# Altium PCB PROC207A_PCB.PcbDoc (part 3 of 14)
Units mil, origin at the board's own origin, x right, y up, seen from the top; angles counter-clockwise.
Board outline 4094.49 x 3724.79 mil, 8 copper layers (Top Layer, L2_GND1, L3_SIG1, L4_PWR1, L5_PWR2, L6_SIG2, L7_GND2, Bottom Layer), stack 58.1 mil thick; 584 components, 399 nets, 8440 pads, 5258 vias.
Unrouted connection lines stored in the file: 9.
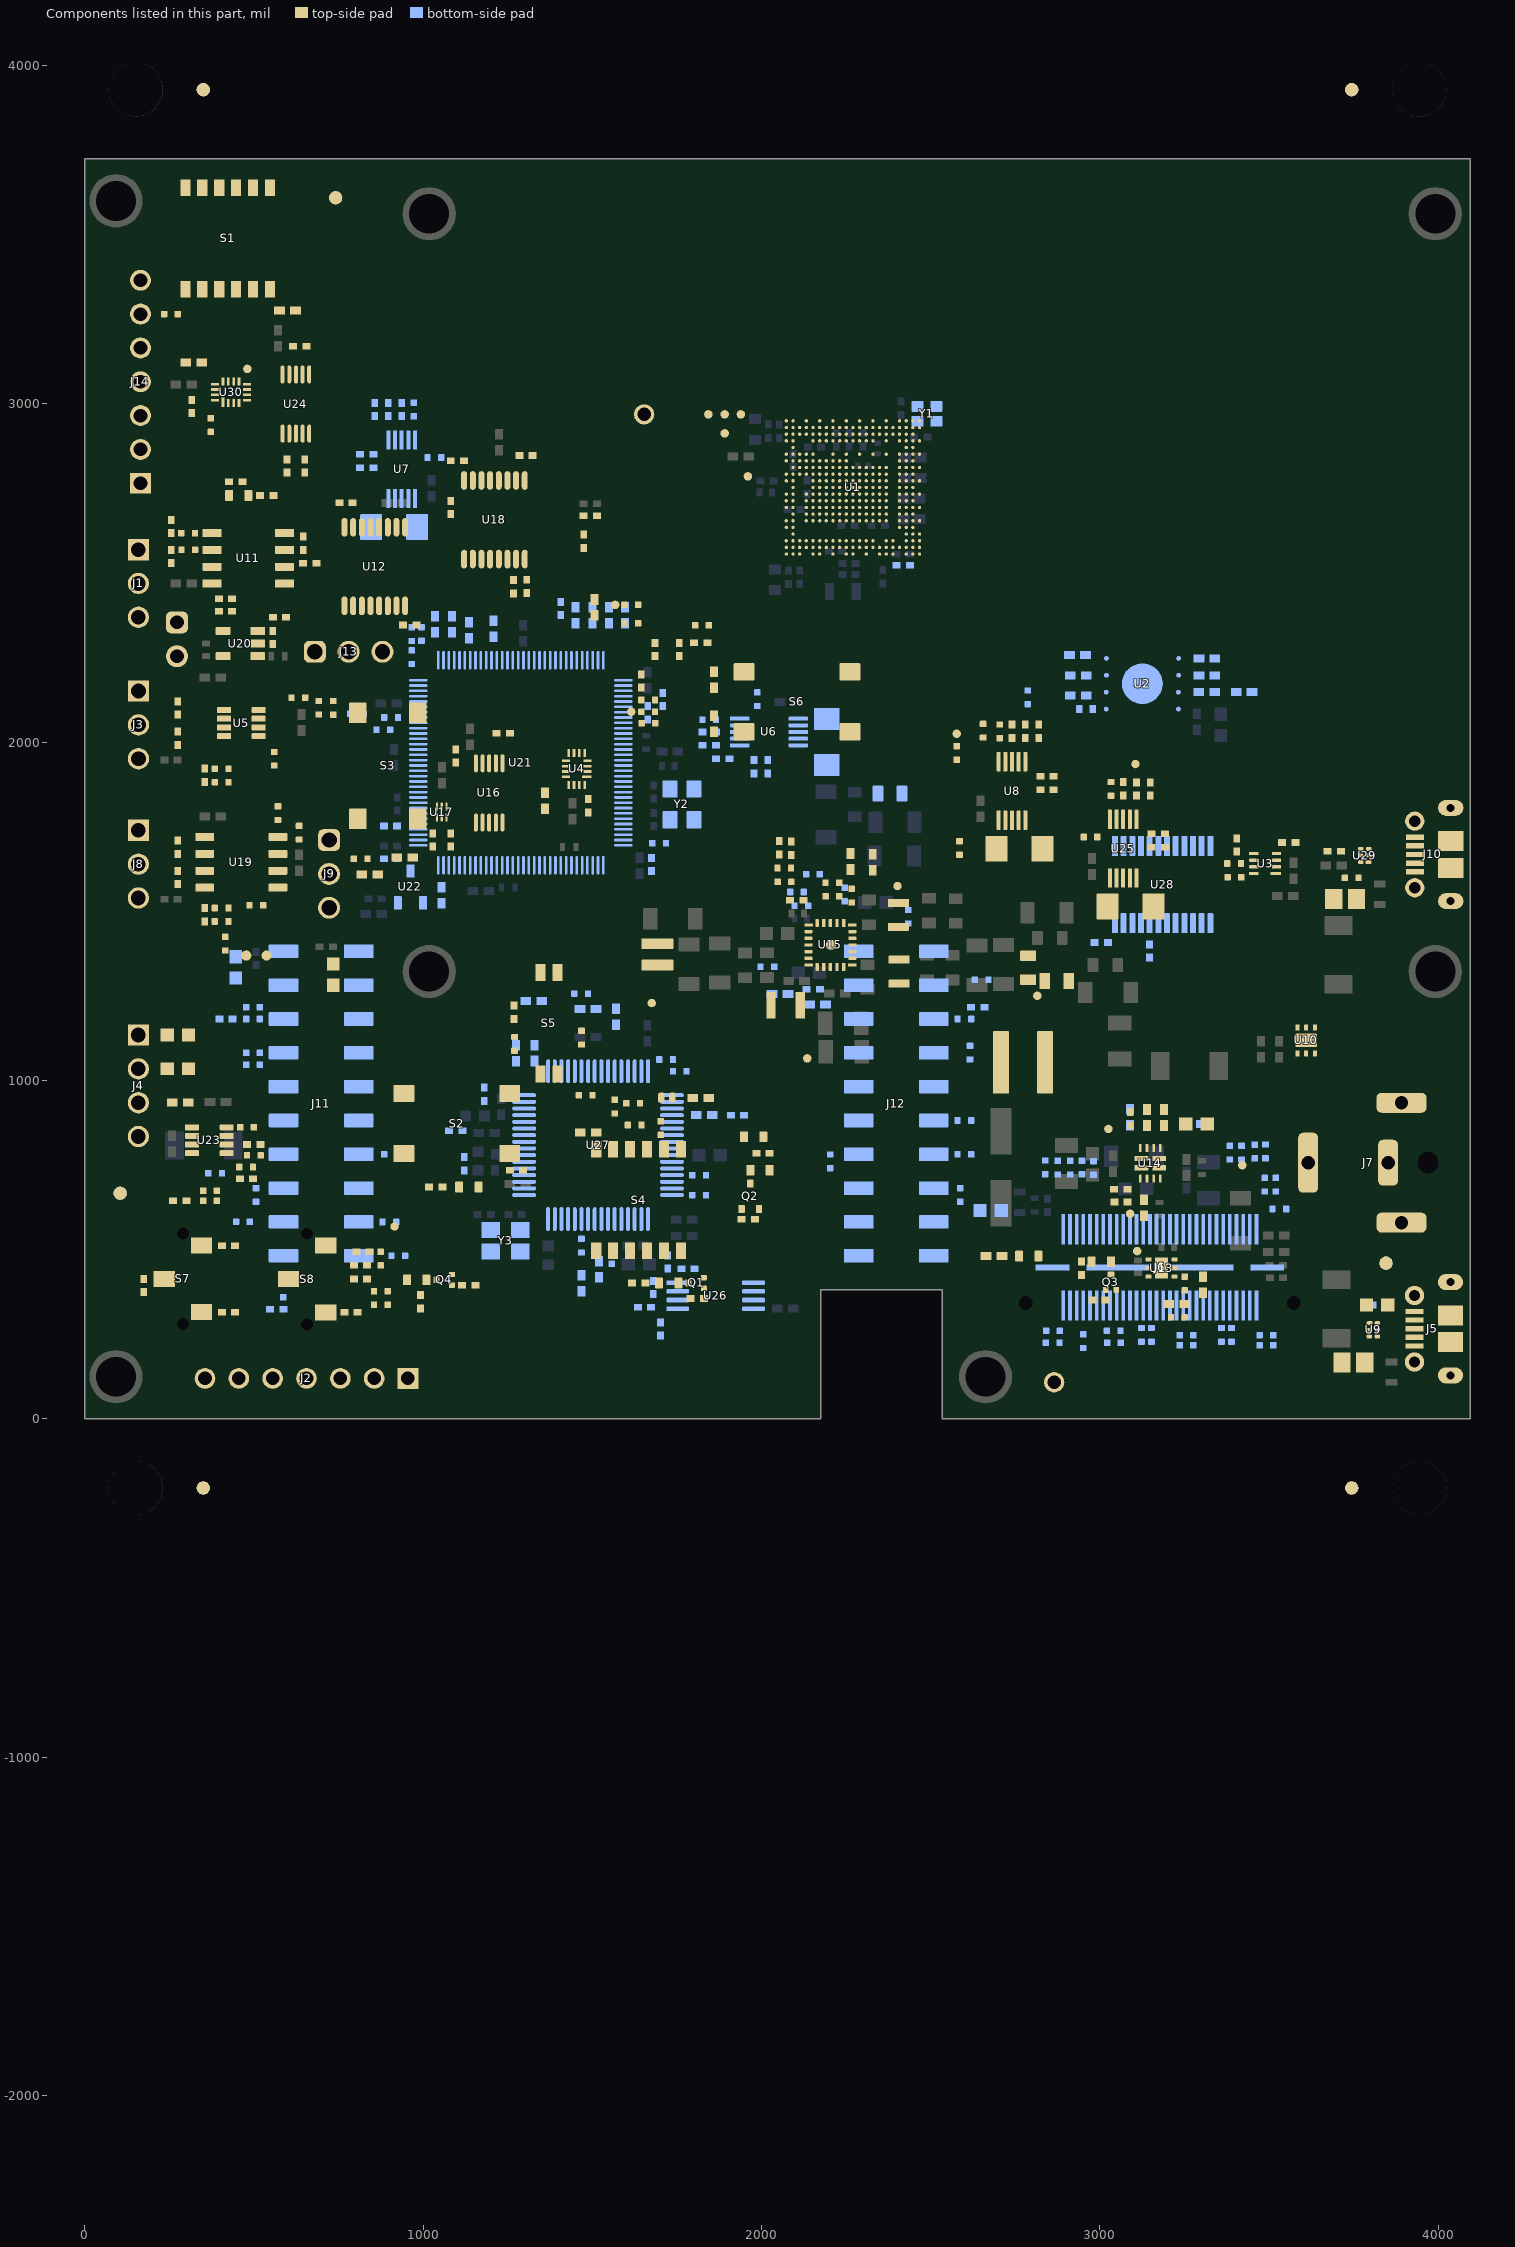
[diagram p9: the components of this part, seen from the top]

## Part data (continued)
D3 D5 D6 D7 D9 D10 D11 D13: library part CMP-0121062-1, "Yellow 589nm LED Indication - Discrete 2.1V 0603 (1608 Metric)", Color=Yellow, Digikey Part Number=751-TLMY1100-GS15CT-ND, Forward Current=20mA, Manufacturer=Vishay, Mouser Part Number=78-TLMY1100-GS15, Operating Temperature Range="-40°C to +100°C", Power_TotalModule=90mW
D4: library part CMP-0078187-3, "Diode, Schottky,  V, 0.01 A, SOD-882", Manufacturer="Skyworks Solutions", Value1=0.01A, Value2=0.34V
FB1 FB2 FB3: library part CMP-0091544-1, "30 Ohms @ 100MHz 1 Power Line Ferrite Bead 0805 (2012 Metric) 6A 10mOhm", Digikey Part Number=445-172906-1-ND, Impedance At Frequency="30Ω @ 100MHz", Manufacturer=TDK, Mouser Part Number=810-MPZ2012S300ATD25, Operating Temperature Range="-55°C to +125°C", Test Frequency=100MHz
FID1 FID2 FID3 FID4 FID5 FID6 FID11 FID11_1 FID11_2 FID11_3 FID15 FID15_1 FID15_2 FID15_3: library part CMP-0077181-1, "Fiducial mark.  There is nothing to buy or mount.", Manufacturer=N/A
J1 J3 J8: library part CMP-0054795-1, "Header, 2.54 mm, 3x1, Gold, R/A, TH", Color=Black, Manufacturer="Wurth Elektronik", Supplier Part Number 1=732-5336-ND
J2: library part CMP-0054584-1, "Header, 2.54 mm, 7x1, Gold, TH", Color=Black, Current_A=3A, Manufacturer="Sullins Connector Solutions", Supplier Part Number 1=S1011E-07-ND, Voltage_V=1.8kV
J4: library part CMP-0054797-1, "Header, 2.54 mm, 4x1, Gold, R/A, TH", Color=Black, Manufacturer="Wurth Elektronik", Supplier Part Number 1=732-5337-ND
J5 J10: library part CMP-0055293-1, "Connector, Receptacle, Micro-USB Type B, R/A, Bottom Mount SMT", Manufacturer=Molex, Supplier Part Number 1=WM1399CT-ND
J6: library part CMP-0075524-1, "Receptacle, 0.5 mm, 30x2, Gold, TH", Color=Black, Manufacturer=Samtec, Supplier Part Number 1=SAM8180-ND
J7: library part CMP-0079472-1, "DC POWER JACK, R/A, TH", Color=Black, Current_A=8A, Manufacturer="CUI Inc.", Supplier Part Number 1=CP-063AH-ND, Voltage_V=24V
J9 J13: library part CMP-0054796-4, "Header, 2.54 mm, 3x1, Gold, TH", Manufacturer="Wurth Elektronik", Supplier Part Number 1=732-5316-ND
J11 J12: library part CMP-0078182-1, "Receptacle, 2.54mm, 10x2, Gold with Tin tail, SMT", Color=Black, Current_A=5.2A, Manufacturer=Samtec, Supplier Part Number 1=SAM1150-10-ND, Voltage_V=405V
J14: library part CMP-0120118-1, Current_A=4A, Digikey Part Number=WM50015-07-ND, Manufacturer=Molex, Mouser Part Number=538-22-28-8072, Operating Temperature Range="-40°C to +80°C", Voltage_V=600V
J15: library part CMP-0080367-2, "Solder Jumper, SMT", Manufacturer=NA
L1: library part CMP-0094298-1, "Shielded Power Inductor 4.7uH 16mOhms 9.7A", Digikey Part Number=2457-XGL5050-472MEC-ND, Manufacturer=Coilcraft, Operating Temperature Range=to, Self Resonant Frequency=25MHz, Test Frequency=1MHz, Tolerance_%=20%
L2 L3 L7: library part CMP-0081523-1, "Ferrite Bead, 600 ohm @ 100 MHz, 0.3 A, 0402", Manufacturer=MuRata, Supplier Part Number 1=490-3998-1-ND, Value1="0.7 ohm", Value2=0.3A, ValueDisplayed="600 ohm"
L4: library part CMP-0095018-1, "100nH Shielded Multilayer Inductor 4A 19mOhm Max 0806 (2016 Metric)", Digikey Part Number=490-LQM2MPZR10MJHLCT-ND, Manufacturer=Murata, Mouser Part Number=81-LQM2MPZR10MJHL, Operating Temperature Range="-55°C to +125°C", Self Resonant Frequency=200MHz, Test Frequency=1MHz, Tolerance_%=20%
L5: library part CMP-0121156-1, "1.5 µH Shielded Thin Film Inductor 3.1 A 60mOhm Max 1008 (2520 Metric)", Digikey Part Number=445-TFM252012ALVA1R5MTAACT-ND, Manufacturer=TDK, Mouser Part Number=810-TFM252012ALVA1R5, Operating Temperature Range="-55°C to +150°C", Test Frequency=1MHz, Tolerance_%=20%
L6 L11: library part CMP-0081095-1, "Inductor, Shielded, Metal Composite, 470 nH, 3.9 A, 0.039 ohm, AEC-Q200 Grade 0, SMD", Manufacturer=TDK, Supplier Part Number 1=445-174573-1-ND, Value1="0.039 ohm", Value2=3.9A, ValueDisplayed=470nH
L8 L9: library part CMP-0003364-1, "Ferrite Bead, 30 ohm @ 100 MHz, 4 A, 0805", Manufacturer=MuRata, Supplier Part Number 1=490-11049-1-ND, Value1="0.014 ohm", Value2=4A, ValueDisplayed="30 ohm"
L14: library part CMP-0078934-1, "Inductor, Ferrite Bead, Ferrite, 2.2 A, 0.035 ohm, AEC-Q200 Grade 1, SMD", Manufacturer=MuRata, Supplier Part Number 1=490-16506-1-ND, Value1="0.035 ohm", Value2=2.2A
LBL1: library part CMP-0003625-1, "Thermal Transfer Printable Labels, 0.650\" W x 0.200\" H - 10,000 per roll", Manufacturer=Brady, Supplier Part Number 1=97C5133
Logo1: library part CMP-0074838-1, "Texas Instrument Corporate Signature"
Logo2: library part CMP-0074844-1
Logo3: library part CMP-0074847-1, "FCC_disclaimer"
Logo4: library part CMP-0074769-1
P1: library part CMP-0075405-3, "Header, 100mil, 2x1, Gold, TH", Color=Black, Current_A=6.3A, Manufacturer=Samtec, Supplier Part Number 1=SAM1029-02-ND, Voltage_V=550V
Q1 Q3 Q4: library part CMP-0091833-1, "N-Channel 20V 250mA (Ta) 500mW (Ta) Surface Mount VESM", Digikey Part Number=SSM3K35AMFVL3FCT-ND, Drain To Source Breakdown Voltage=20V, Input Capacitace At Vds="18pF @ 10V", Manufacturer=Toshiba, Mouser Part Number=757-SSM3K35AMFVL3F, Operating Temperature Range="to +150°C", Power_W=150mW, Pulse Drain Current=600mA, Typ Forward Diode Voltage=0.8V
Q2: library part CMP-0000948-2, "MOSFET, N-CH, 100 V, 0.17 A, SOT-323", Alternate Manufacturer=None, Manufacturer="Diodes Inc.", Supplier Part Number 1=BSS123W-FDICT-ND, Value1=1
R1 R30 R31 R32 R154 R155: library part CMP-0025884-3, "RES, 0, 5%, 0.125 W, 0603", Manufacturer=Vishay/Beyschlag, Power_W=125mW, Supplier Part Number 1=MCT0603-0.0-ZZCT-ND, TempCo=ppm/C, Tolerance_%=5%, Value2=0.125W, Value_Code=0000, ValueDisplayed=0
R2 R5 R7 R8 R9 R10 R12 R14 R17 R22 R27 R44 R49 R54 R57 R65 R71 R72 R73 R82 R86 R94 R95 R97 R98 R101 R103 R104 R105 R106 R107 R112 R113 R114 R115 R116 R117 R123 R127 R128 R135 R136 R138 R142 R144 R148 R150 R151 R157 R158 R161 R162 R164 R165 R166 R167 R168 R184 R203 R206 R218 R231 R247 R250 R253 R261 R271 R276 R283 R288: library part CMP-0025958-3, "RES, 10.0 k, 1%, 0.063 W, AEC-Q200 Grade 0, 0402", Manufacturer=Vishay-Dale, Power_W=63mW, Supplier Part Number 1=541-10.0KLCT-ND, TempCo="100 ppm/C", Tolerance_%=1%, Value2=0.063W, Value_Code=10k0, ValueDisplayed=10.0k
R3 R15 R18 R19 R24 R25 R26 R29 R34 R37 R38 R39 R40 R41 R42 R43 R52 R53 R55 R56 R58 R59 R60 R61 R62 R63 R67 R69 R77 R78 R80 R81 R83 R85 R88 R89 R90 R91 R96 R100 R102 R108 R109 R110 R111 R118 R119 R120 R121 R129 R131 R132 R133 R137 R139 R143 R152 R153 R159 R160 R170 R175 R176 R177 R178 R180 R181 R182 R183 R188 R189 R190 R197 R198 R199 R201 R210 R211 R212 R214 R216 R217 R219 R220 R221 R222 R223 R224 R225 R226 R227 R228 R229 R230 R232 R235 R238 R240 R241 R242 R243 R244 R245 R254 R257 R259 R264 R266 R267 R268 R269 R270 R273 R278 R279 R280 R281 R282 R284 R285 R286 R290: library part CMP-0002710-1, "0 Ohms Jumper Chip Resistor 0402 (1005 Metric) Automotive AEC-Q200 Thick Film", Digikey Part Number=P0.0JCT-ND, Manufacturer=Panasonic, Mouser Part Number=667-ERJ-2GE0R00X, Operating Temperature Range="-55°C to +155°C", Power=100mW
R4: library part CMP-0026959-2, "RES, 62 k, 5%, 0.063 W, 0402", Manufacturer=Vishay-Dale, Power_W=63mW, Supplier Part Number 1=541-62KJCT-ND, TempCo="200 ppm/C", Tolerance_%=5%, Value2=0.063W, Value_Code=62k0, ValueDisplayed=62k
R6 R20 R23 R74 R75 R145 R272: library part CMP-0026739-1, "RES, 4.70 k, 1%, 0.0625 W, 0402", Manufacturer="Yageo America", Power_W=62.5mW, Supplier Part Number 1=311-4.7KLRCT-ND, TempCo="100 ppm/C", Tolerance_%=1%, Value2=0.0625W, Value_Code=4k70, ValueDisplayed=4.70k
R11 R92 R99 R146 R147 R149 R156 R163 R173 R215 R246 R255 R256 R265 R274 R275: library part CMP-0025950-3, "RES, 100 k, 1%, 0.063 W, AEC-Q200 Grade 0, 0402", Manufacturer=Vishay-Dale, Power_W=63mW, Supplier Part Number 1=541-100KLCT-ND, TempCo="100 ppm/C", Tolerance_%=1%, Value2=0.063W, Value_Code=100k
R13 R16: library part CMP-0026542-2, "RES, 750, 1%, 0.063 W, AEC-Q200 Grade 0, 0402", Manufacturer=Vishay-Dale, Power_W=63mW, Supplier Part Number 1=541-750LCT-ND, TempCo="100 ppm/C", Tolerance_%=1%, Value2=0.063W, Value_Code=750R, ValueDisplayed=750
R21 R70 R76 R174 R191 R194 R195 R196 R233 R237 R277: library part CMP-0026657-1, "RES, 1.00 k, 1%, 0.1 W, 0402", Manufacturer=Panasonic, Power_W=100mW, Supplier Part Number 1=P1.00KLCT-ND, TempCo="100 ppm/C", Tolerance_%=1%, Value2=0.1W, Value_Code=1k00, ValueDisplayed=1.00k
R28 R64 R66 R141 R171 R172 R179 R252 R258 R263 R287: library part CMP-0078212-1, "RES, 510, 5%, 0.1 W, AEC-Q200 Grade 0, 0402", Manufacturer=Panasonic, Power_W=100mW, Supplier Part Number 1=P510JCT-ND, TempCo="200 ppm/C", Tolerance_%=5%, Value2=0.1W, Value_Code=510R, ValueDisplayed=510
R33: library part CMP-0026171-2, "RES, 21.5 k, 1%, 0.063 W, AEC-Q200 Grade 0, 0402", Manufacturer=Vishay-Dale, Power_W=63mW, Supplier Part Number 1=541-21.5KLCT-ND, TempCo="100 ppm/C", Tolerance_%=1%, Value2=0.063W, Value_Code=21k5, ValueDisplayed=21.5k
R35: library part CMP-0026187-2, "RES, 23.7 k, 1%, 0.063 W, AEC-Q200 Grade 0, 0402", Manufacturer=Vishay-Dale, Power_W=63mW, Supplier Part Number 1=541-23.7KLCT-ND, TempCo="100 ppm/C", Tolerance_%=1%, Value2=0.063W, Value_Code=23k7, ValueDisplayed=23.7k
R36: library part CMP-0023704-1, "RES, 12.1 k, 0.1%, 0.1 W, 0603", Manufacturer="Yageo America", Power_W=100mW, TempCo="25 ppm/C", Tolerance_%=0.1%, Value2=0.1W, Value_Code=12k1, ValueDisplayed=12.1k
R45 R46 R47 R48 R51 R93 R122 R124 R125 R126 R186 R187 R209 R248 R249 R251: library part CMP-0026299-2, "RES, 33.2, 1%, 0.063 W, AEC-Q200 Grade 0, 0402", Manufacturer=Vishay-Dale, Power_W=63mW, Supplier Part Number 1=541-33.2LCT-ND, TempCo="100 ppm/C", Tolerance_%=1%, Value2=0.063W, Value_Code=33R2, ValueDisplayed=33.2
R50: library part CMP-0120015-1, "General Purpose Chip Resistor Thick Film 0402 47.5kOhm 1% Paper T/R", Digikey Part Number=13-RC0402FR-1047K5LCT-ND, Manufacturer=YAGEO, Mouser Part Number=603-RC0402FR-1047K5L, Operating Temperature Range="-55°C to +155°C", Power_W=63mW, TempCo=100ppm/°C, Tolerance_%=1%
R68 R79 R130 R140: library part CMP-0026491-2, "RES, 61.9, 1%, 0.063 W, AEC-Q200 Grade 0, 0402", Manufacturer=Vishay-Dale, Power_W=63mW, Supplier Part Number 1=541-61.9LCT-ND, TempCo="100 ppm/C", Tolerance_%=1%, Value2=0.063W, Value_Code=61R9, ValueDisplayed=61.9
R84: library part CMP-0026099-2, "RES, 1.96 k, 1%, 0.063 W, AEC-Q200 Grade 0, 0402", Manufacturer=Vishay-Dale, Power_W=63mW, Supplier Part Number 1=541-1.96KLCT-ND, TempCo="100 ppm/C", Tolerance_%=1%, Value2=0.063W, Value_Code=1k96, ValueDisplayed=1.96k
R87: library part CMP-0025964-3, "RES, 10.2, 1%, 0.063 W, AEC-Q200 Grade 0, 0402", Manufacturer=Vishay-Dale, Power_W=63mW, Supplier Part Number 1=541-10.2LCT-ND, TempCo="100 ppm/C", Tolerance_%=1%, Value2=0.063W, Value_Code=10R2, ValueDisplayed=10.2
R134: library part CMP-0121430-1, "10 mOhms ±1% 0.25W, 1/4W Chip Resistor Automotive AEC-Q200, Current Sense, Moisture Resistant, Pulse Withstanding Metal Element", Digikey Part Number=541-WSL1206R0100FEBCT-ND, Manufacturer="Vishay Dale", Mouser Part Number=71-WSL1206-0.01-E3, Octopart Part Number=b6137d47e1ab69d4, Operating Temperature Range="-65°C to +170°C", Power_W=250mW, TempCo=75ppm/°C, Tolerance_%=1%, Voltage=50mV
R169: library part CMP-0026993-2, "RES, 100, 5%, 0.1 W, AEC-Q200 Grade 0, 0402", Manufacturer=Panasonic, Power_W=100mW, Supplier Part Number 1=P100JCT-ND, TempCo="200 ppm/C", Tolerance_%=5%, Value2=0.1W, Value_Code=100R, ValueDisplayed=100
R185: library part CMP-0026890-5, "RES, 2.2 k, 5%, 0.063 W, AEC-Q200 Grade 0, 0402", Manufacturer=Vishay-Dale, Power_W=63mW, Supplier Part Number 1=541-2.2KJCT-ND, TempCo="200 ppm/C", Tolerance_%=5%, Value2=0.063W, Value_Code=2k20, ValueDisplayed=2.2k
R192 R200: library part CMP-0098431-1, "40 mOhms ±1% 0.25W, 1/4W Chip Resistor Automotive AEC-Q200, Current Sense, Moisture Resistant, Pulse Withstanding Metal Element", Digikey Part Number=WSL1206R0400FEB-ND, Manufacturer=Vishay, Mouser Part Number=71-WSL1206-0.04-E3, Operating Temperature Range="-65°C to +170°C", Power_W=250mW, TempCo=75ppm/°C, Tolerance_%=1%
R193: library part CMP-0098430-1, "Res Metal Strip 1206 0.02 Ohm 1% 1/4W ±75ppm/°C Molded SMD SMD T/R", Digikey Part Number=541-WSL1206R0200FEBCT-ND, Manufacturer="Vishay Dale", Mouser Part Number=71-WSL1206-0.02-E3, Octopart Part Number=bfee76eb40e46029, Operating Temperature Range="-65°C to +170°C", Power_W=250mW, TempCo=75ppm/°C, Tolerance_%=1%
R202: library part CMP-0026404-2, "RES, 49.9, 1%, 0.063 W, AEC-Q200 Grade 0, 0402", Manufacturer=Vishay-Dale, Power_W=63mW, Supplier Part Number 1=541-49.9LCT-ND, TempCo="100 ppm/C", Tolerance_%=1%, Value2=0.063W, Value_Code=49R9, ValueDisplayed=49.9
R204 R207: library part CMP-0026557-2, "RES, 7.87 k, 1%, 0.063 W, AEC-Q200 Grade 0, 0402", Manufacturer=Vishay-Dale, Power_W=63mW, Supplier Part Number 1=541-7.87KLCT-ND, TempCo="100 ppm/C", Tolerance_%=1%, Value2=0.063W, Value_Code=7k87, ValueDisplayed=7.87k
R205 R208: library part CMP-0026574-2, "RES, 82.5 k, 1%, 0.063 W, AEC-Q200 Grade 0, 0402", Manufacturer=Vishay-Dale, Power_W=63mW, Supplier Part Number 1=541-82.5KLCT-ND, TempCo="100 ppm/C", Tolerance_%=1%, Value2=0.063W, Value_Code=82k5, ValueDisplayed=82.5k
R213 R262: library part CMP-0026878-3, "RES, 220, 5%, 0.063 W, AEC-Q200 Grade 0, 0402", Manufacturer=Vishay-Dale, Power_W=63mW, Supplier Part Number 1=541-220JCT-ND, TempCo="200 ppm/C", Tolerance_%=5%, Value2=0.063W, Value_Code=220R, ValueDisplayed=220
R234: library part CMP-0026413-2, "RES, 4.87 k, 1%, 0.063 W, AEC-Q200 Grade 0, 0402", Manufacturer=Vishay-Dale, Power_W=63mW, Supplier Part Number 1=541-4.87KLCT-ND, TempCo="100 ppm/C", Tolerance_%=1%, Value2=0.063W, Value_Code=4k87, ValueDisplayed=4.87k
R236 R239: library part CMP-0078210-2, "RES, 330 k, 1%, 0.063 W, AEC-Q200 Grade 0, 0402", Manufacturer=Vishay-Dale, Power_W=63mW, Supplier Part Number 1=541-330KLCT-ND, TempCo="100 ppm/C", Tolerance_%=1%, Value2=0.063W, Value_Code=330k
R260: library part CMP-0078244-2, "RES, 30.0 k, 1%, 0.063 W, AEC-Q200 Grade 0, 0402", Manufacturer=Vishay-Dale, Power_W=63mW, Supplier Part Number 1=541-30.0KLCT-ND, TempCo="100 ppm/C", Tolerance_%=1%, Value2=0.063W, Value_Code=30k0, ValueDisplayed=30.0k
R289: library part CMP-0026067-3, "RES, 19.1 k, 1%, 0.063 W, AEC-Q200 Grade 0, 0402", Manufacturer=Vishay-Dale, Power_W=63mW, Supplier Part Number 1=541-19.1KLCT-ND, TempCo="100 ppm/C", Tolerance_%=1%, Value2=0.063W, Value_Code=19k1, ValueDisplayed=19.1k
S1 S4: library part CMP-0002304-1, "Switch, SPST, Slide, Off-On, 6 Pos, 0.025A, 24V, SMD", CurrentRating_mA=25A, Manufacturer="CTS Electrocomponents", Supplier Part Number 1=CT2186LPST-ND
S2 S3 S6: library part CMP-0079642-1, "Switch, SPST-NO, Off-Mom, 0.05 A, 12 VDC, SMD", CurrentRating_mA=50A, Manufacturer="C&K Components", Supplier Part Number 1=CKN9112CT-ND
S5: library part CMP-0002230-1, "Switch, SPST, 2 Pos, 25mA, 24VDC, SMD", CurrentRating_mA=25A, Manufacturer="CTS Electrocomponents", Supplier Part Number 1=CT2182LPST-ND
S7 S8: library part CMP-0002183-2, "Switch, Slide, SPDT, 0.2A, J Lead, SMD", CurrentRating_mA=200A, Manufacturer="Copal Electronics", Supplier Part Number 1=563-1314-1-ND
TP1 TP2 TP3 TP4 TP5 TP6 TP7 TP8 TP9 TP11 TP12 TP13 TP14 TP15 TP16 TP17 TP18 TP19 TP20 TP21 TP22: library part CMP-0078143-3, "TEST POINT.  No entry in BOM.", Manufacturer=N/A
U1: library part CMP-0122984-4, Manufacturer="Texas Instruments", Operating Temperature Range=to
U2: library part CMP-0093403-2, "NOR Flash 16Mbit 16M x 1/8M x 2/4M x 4 Serial-SPI 3.3V 8-Pin WSON", Frequency_Fixed=80MHz, Manufacturer=Macronix, Max Supply Voltage=3.6V, Min Supply Voltage=2.3V, Operating Temperature Range="-40°C to +85°C"
U3: library part CMP-0074317-1, "Automotive Grade, 1.7V Remote and Local Temp Sensor with N-Factor, Filtering and Series-R Correction, DQF0008A (WSON-8)", Alternate Manufacturer="Texas Instruments"
U4 U30: library part CMP-0067415-1, "10-Ohm Quad SPDT Analog Switch, RSV0016A (UQFN-16)", Alternate Manufacturer="Texas Instruments"
U5: library part CMP-0122870-1, "Enhanced automotive CAN transceiver with standby and 1.8-V I/O support 8-SOT-23-THIN -40 to 150", Digikey Part Number=296-TCAN1044AVDDFRQ1CT-ND, Manufacturer="Texas Instruments", Max Supply Voltage=5.5V, Min Supply Voltage=1.7V, Mouser Part Number=595-TCAN1044AVDDFRQ1, Operating Temperature Range="-40°C to +150°C"
U6 U7 U8 U25: library part CMP-0098432-1, "Current Sense Amplifier 1 Circuit 10-VSSOP", Digikey Part Number=296-INA228AIDGSTCT-ND, Input Bias Current=0.01uA, Input Offset Voltage=1mV, Manufacturer="Texas Instruments", Max Supply Voltage=5.5V, Min Supply Voltage=2.7V, Mouser Part Number=595-INA228AIDGST, Nominal Supply Current=640uA, Operating Temperature Range="-40°C to +125°C"
U9 U29: library part CMP-0043115-3, "4-Channel ESD Protection Array for High-Speed Data Interfaces, DRY0006A (USON-6)", Breakdown Voltage(Min)(V)=6, IO Capacitance(Typ)(pF)=1.6, IO Leakage Current(nA)=1, Manufacturer="Texas Instruments", Operating Temperature Range="-40 to 85 C", Rating=Catalog
U10: library part CMP-0077835-1, "18-V Precision Surge Protection Clamp, DRV0006A (WSON-6)", Alternate Manufacturer="Texas Instruments"
U11: library part CMP-0005309-2, "IC, EEPROM, 8KBIT, 400KHZ, 8SOIC", Manufacturer="ON Semiconductor", Supplier Part Number 1=CAT24C08WI-GT3CT-ND
U12 U18: library part CMP-0067412-1, "0.45-Ohm Quad SPDT Analog Switch Quad-Channel 2:1 Multiplexer/Demultiplexer with Two Controls, PW0016A (TSSOP-16)", Alternate Manufacturer="Texas Instruments"
U13: library part CMP-0013427-7, "500mA LDO, DRV0006A (WSON-6)", Alternate Manufacturer="Texas Instruments"
U14: library part CMP-0078351-3, "2.7V-22V, 4A, 50mohm Priority Power MUX, RUX0012A (VQFN-HR-12)", Alternate Manufacturer="Texas Instruments", Alternate PartNumber=TPS2121RUXT
U15: library part CMP-0123008-1, "Automotive Camera, Radar and MCU PMIC", Manufacturer="Texas Instruments", Max Supply Voltage=35V, Min Supply Voltage=4V, Operating Temperature Range="-40°C to +125°C", Output Voltage=3-5.5V
U16 U24: library part CMP-0067410-1, "0.65 Ohm Dual SPDT Analog Switch Dual-Channel 2:1 Multiplexer/Demultiplexer, DGS0010A (VSSOP-10)", Alternate Manufacturer="Texas Instruments"
U17: library part CMP-0051215-4, "Single 3-Input Positive-AND Gate, DSF0006A, LARGE T&R", F @ Nom Voltage(Max)(Mhz)=150, Generic Part Number=SN74LVC1G11, ICC @ Nom Voltage(Max)(mA)=0.01, Manufacturer="Texas Instruments", Operating Temperature Range(C)="-40 to 125,-40 to 85", Rating=Catalog, tpd @ Nom Voltage(Max)(ns)=20,7.8,6.2,4.6, Voltage(Nom)(V)=1.8,2.5,3.3,5
U19: library part CMP-0121020-1, "Dual, Simultaneous-Sampling, 16-Bit, 5 MSPS SAR ADCs", Manufacturer="Texas Instruments", Max Supply Voltage=3.6V, Min Supply Voltage=1.7V, Operating Temperature Range="-40°C to +150°C"
U20: library part CMP-0092338-1, "Linear Voltage Regulator IC Positive Fixed Output 300mA SOT-23-5", Digikey Part Number=296-TPS78417QDBVRQ1CT-ND, Dropout Voltage=900mV, Manufacturer="Texas Instruments", Max Supply Voltage=6V, Min Supply Voltage=1.65V, Mouser Part Number=595-TPS78417QDBVRQ1, Nominal Supply Current=0.033mA, Operating Temperature Range="-40°C to +150°C", Output Voltage=1.7V
U21: library part CMP-0029856-2, "Tiva C Series Microcontroller, 1024 KB Flash, 256 KB SRAM, 12 Bit, 20 Channels, -40 to 105 degC, 128-Pin TQFP (PDT), Green (RoHS & no Sb/Br), Tray", Manufacturer="Texas Instruments", Temperature Range="-40 to 105 degC"
U22: library part CMP-0033001-1, "Precision Micropower Shunt Voltage Reference, 0.5% accuracy, 2.5 V, 15 ppm / degC, 15 mA, -40 to 125 degC, 3-pin SOT-23 (DBZ), Green (RoHS & no Sb/Br)", Manufacturer="Texas Instruments", Rating=Catalog, Temp Coeff(Max)(ppm/ degree C)=100, Temp Coeff(Typ)(ppm/ degree C)=15
U23: library part CMP-0090433-1, "Local Interconnect Network (LIN) Transceiver with Dominant State Timeout", Manufacturer="Texas Instruments", Max Supply Voltage=36V, Min Supply Voltage=4.5V, Nominal Supply Current=0.3-1.2mA, Operating Temperature Range="-40°C to +150°C"
U26: library part CMP-0081524-1, "1K Microwire Compatible Serial EEPROM, TSSOP-8", Manufacturer=Microchip, Supplier Part Number 1=93LC46B-I/ST-ND
U27: library part CMP-0004747-1, "Quad High Speed USB to Multipurpose UART/MPSSE IC", Manufacturer=FTDI, Supplier Part Number 1=768-1026-1-ND
U28: library part CMP-0092155-1, "3.3-V, 2:1 (SPDT), 6-channel analog multiplexer with 1.8-V compatible control inputs 24-TSSOP -40 to 85", Digikey Part Number=296-24570-1-ND, Manufacturer="Texas Instruments", Max Supply Voltage=3.6V, Min Supply Voltage=1.65V, Mouser Part Number=595-TS3A27518EPWR, Nominal Supply Current=0.01-0.04uA, Octopart Part Number=cf0206a9c1b910c5, On State Resistance=4.4Ω, Operating Temperature Range="-40°C to +85°C"
Y1: library part CMP-0090505-1, "40MHz ±10ppm Crystal 8pF 50 Ohms 4-SMD, No Lead", Alternate Part Number=CX2016SA40000D0PTWC1, Digikey Part Number=FW4000044QDICT-ND, Frequency_Fixed=40MHz, Frequency Stability=50ppm, Frequency Tolerance=10ppm, Load Capacitance=8pF, Manufacturer=Diodes, Mouser Part Number=729-FW4000044Q, Operating Temperature Range="-40°C to +125°C"
Y2: library part CMP-0095014-1, "16 MHz ±15ppm Crystal 8pF 80 Ohms 4-SMD, No Lead", Digikey Part Number=50-ECS-160-8-33Q-RES-CT-ND, Frequency_Fixed=16MHz, Frequency Stability=50ppm, Frequency Tolerance=15ppm, Load Capacitance=8pF, Manufacturer=ECS, Mouser Part Number=520-ECS160833QRES-TR, Operating Temperature Range="-40°C to +125°C"
Y3: library part CMP-0081529-1, "Crystal, 12 MHz, 15 ppm, 8 pF, AEC-Q200 Grade 1, SMD", Frequency Stability="50 ppm", Frequency Tolerance="15 ppm", Frequency_Fixed=12MHz, Load Capacitance="8 pF", Manufacturer=NDK, Supplier Part Number 1=644-1128-1-ND
ZZ1: library part CMP-0003616-3
ZZ2: library part CMP-0077236-1
ZZ3: library part CMP-0077237-1
ZZ4 ZZ5: library part CMP-0077238-1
